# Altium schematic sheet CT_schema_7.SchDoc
size 278 x 170 mm
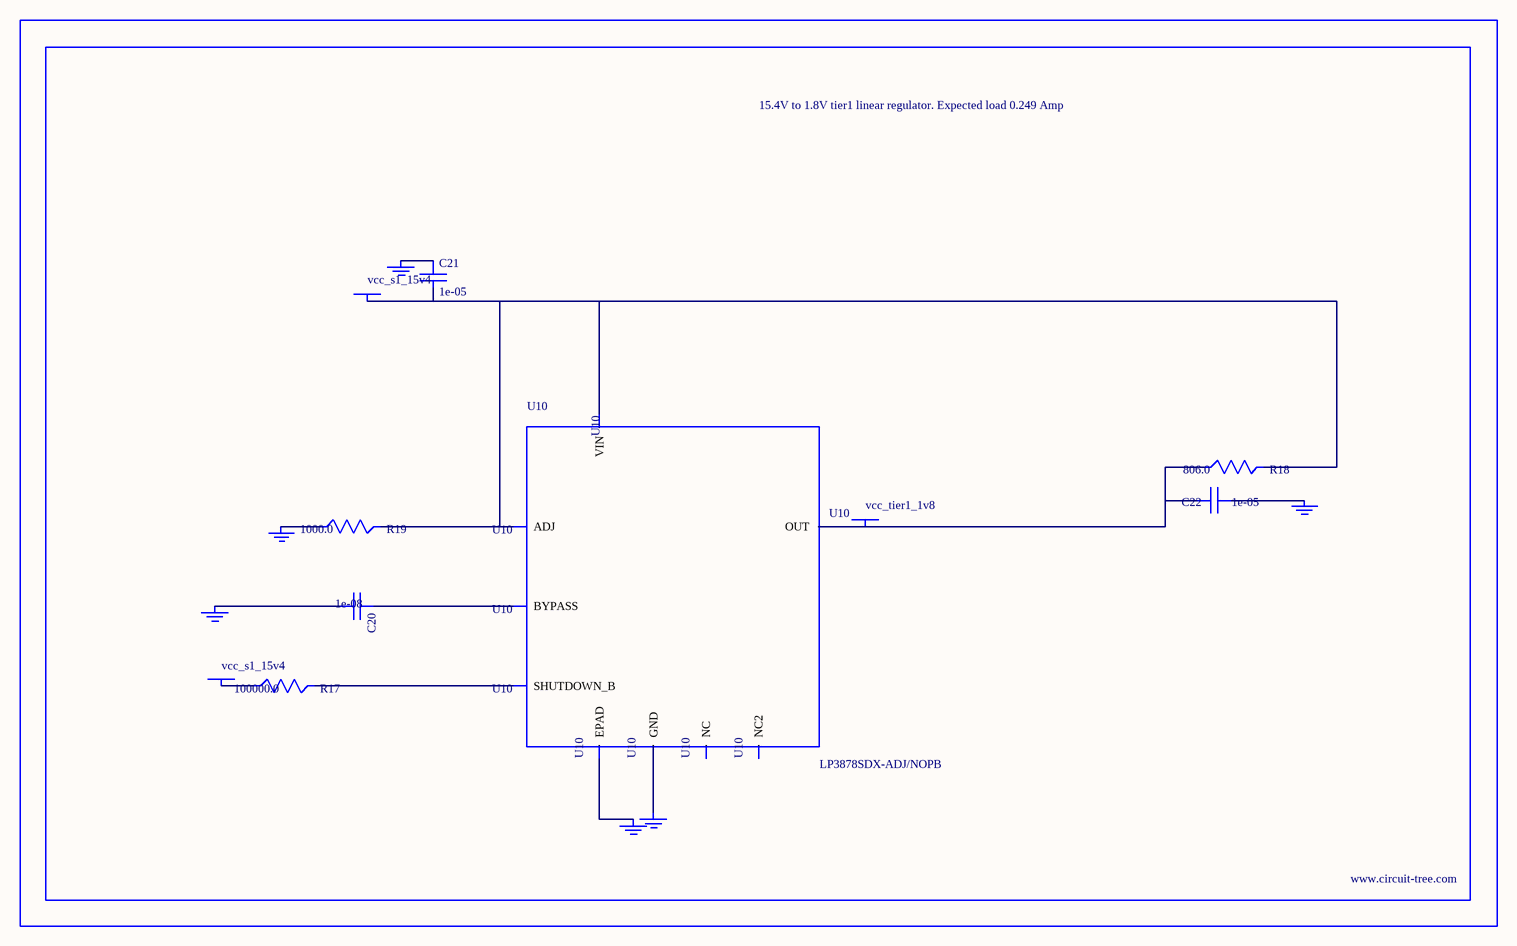
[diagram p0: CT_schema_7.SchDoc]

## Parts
BORDER6  (no value)
C20  1e-08  [C0402]
C21  1e-05  [C1210]
C22  1e-05  [C0805]
GND_INSTANCE_6_0  (no value)
GND_INSTANCE_6_1  (no value)
GND_INSTANCE_6_2  (no value)
GND_INSTANCE_6_3  (no value)
GND_INSTANCE_6_4  (no value)
GND_INSTANCE_6_5  (no value)
POWER_INSTANCE_6_0  vcc_s1_15v4
POWER_INSTANCE_6_1  vcc_s1_15v4
POWER_INSTANCE_6_2  vcc_tier1_1v8
R17  100000.0  [R0603]
R18  806.0  [R0603]
R19  1000.0  [R0603]
U10  LP3878SDX-ADJ/NOPB  [WSON-8]

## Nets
NetC20_1: C20.1 U10.1(BYPASS)
NetC20_2: C20.2 GND_INSTANCE_6_0.0(GND)
NetC21_1: C21.1 GND_INSTANCE_6_1.0(GND)
NetC21_2: C21.2 POWER_INSTANCE_6_0.0(PWR) R18.2 R19.2 U10.4(VIN) U10.6(ADJ)
NetC22_1: C22.1 GND_INSTANCE_6_2.0(GND)
NetC22_2: C22.2 POWER_INSTANCE_6_2.0(PWR) R18.1 U10.5(OUT)
NetGND_INSTANCE_6_3_0: GND_INSTANCE_6_3.0(GND) R19.1
NetGND_INSTANCE_6_4_0: GND_INSTANCE_6_4.0(GND) U10.PAD(EPAD)
NetGND_INSTANCE_6_5_0: GND_INSTANCE_6_5.0(GND) U10.3(GND)
NetPOWER_INSTANCE_6_1_0: POWER_INSTANCE_6_1.0(PWR) R17.1
NetR17_2: R17.2 U10.8(SHUTDOWN_B)

Not connected (* = marked no-connect by the designer): U10 2(NC) 7(NC2)

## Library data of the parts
BORDER6 = BORDER_PAGE6
C20 = C0402C103K3RAC
C21 = C1210C106K5PACTU
C22 = GRM219R60J106ME19D
GND_INSTANCE_6_0-GND_INSTANCE_6_5 = GND
POWER_INSTANCE_6_0-POWER_INSTANCE_6_2 = PWR
R17 = RC0603JR-07100KL
R18 = ERJ-3EKF8060V
R19 = RC0603JR-071KL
